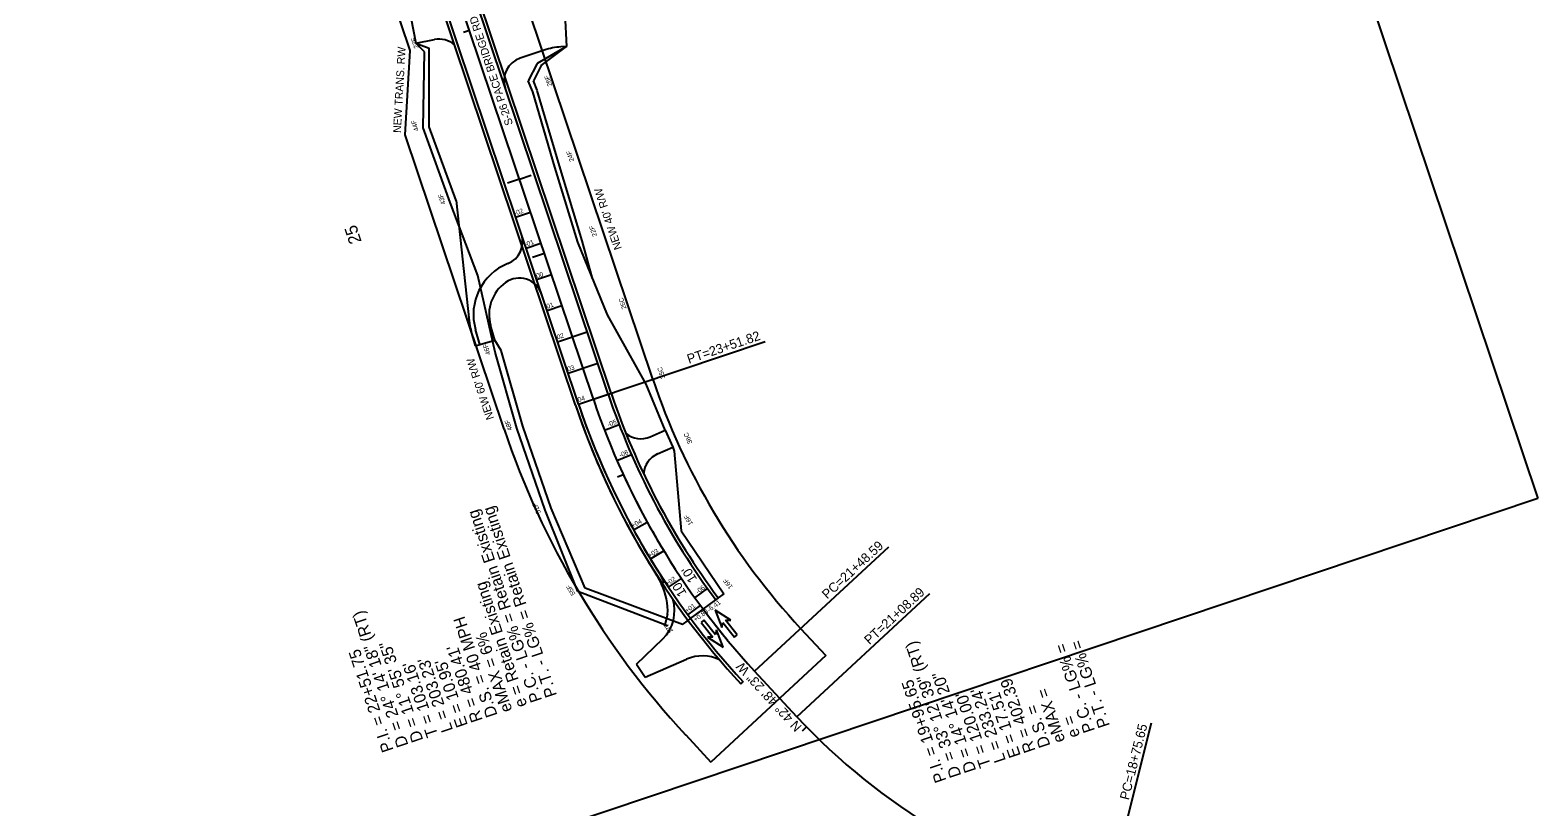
# Model space of a CAD drawing. Extents: x 1528853 to 1624411, y 1119753 to 1162242.
# Drawn here: x 1529554 to 1530516, y 1159228 to 1159723 of the extents above; entities that cross this region are included whole.
import ezdxf

# ---------------------------------------------------------------- set-up
doc = ezdxf.new("R2010")
doc.units = 0
for name, color, linetype in [('RD_EX_Road Text', 7, 'Continuous'), ('RD_HC_Cl', 7, 'Continuous'), ('RD_HC_Data', 7, 'Continuous'), ('RD_HC_Data_Tic', 7, 'Continuous'), ('RD_HC_TX_Sta50', 7, 'Continuous'), ('RD_PD_ALT1_TX', 7, 'Continuous'), ('RD_PD_CstnLmt', 7, 'Continuous'), ('RD_PD_CstnLmt_TX', 7, 'Continuous'), ('RD_PD_DR_ErosCtrl', 7, 'Continuous'), ('RD_PD_Driveway', 7, 'Continuous'), ('RD_PD_Final_TrvlWay', 7, 'Continuous'), ('RD_PD_Final_TX', 7, 'Continuous'), ('RD_PD_PaveShd', 7, 'Continuous'), ('RD_PD_RW', 7, 'Continuous'), ('RD_SHT_ShtClip', 7, 'Continuous'), ('RD_TX_Pipe_ElevEX', 7, 'Continuous')]:
    doc.layers.add(name, color=color, linetype=linetype)

msp = doc.modelspace()

# ---------------------------------------------------------------- linework, layer by layer
at = {"layer": 'RD_HC_Cl'}
for p, q in [((1529913.5, 1159487.74), (1529500.12, 1160718.34)), ((1530043.42, 1159285.14), (1530016.44, 1159314.26))]:
    msp.add_line(p, q, dxfattribs=at)
for centre, radius, start, end in [((1530368.9, 1159640.71), 480.41, 198.56801, 222.80647), ((1530338.63, 1159558.58), 402.39, 222.80647, 256.01743)]:
    msp.add_arc(centre, radius, start, end, dxfattribs=at)
at = {"layer": 'RD_HC_Data'}
for p, q in [((1529913.5, 1159487.74), (1530023.07, 1159524.55)), ((1530016.44, 1159314.26), (1530102.05, 1159393.56)), ((1530043.42, 1159285.14), (1530128.31, 1159363.77)), ((1530241.41, 1159168.11), (1530269.59, 1159281.29))]:
    msp.add_line(p, q, dxfattribs=at)
at = {"layer": 'RD_HC_Data_Tic'}
for p, q in [((1529834.47, 1159723), (1529830.68, 1159721.72)), ((1529866.31, 1159628.2), (1529858.73, 1159625.65)), ((1529866.31, 1159628.2), (1529873.89, 1159630.75)), ((1529932.61, 1159439.6), (1529928.98, 1159437.92)), ((1529983.59, 1159353.78), (1529980.38, 1159351.39)), ((1530049.53, 1159278.68), (1530046.66, 1159275.9))]:
    msp.add_line(p, q, dxfattribs=at)
at = {"layer": 'RD_PD_ALT1_TX'}
for p, q in [((1529863.89, 1159603.99), (1529873.37, 1159607.18)), ((1529870.58, 1159584.09), (1529880.06, 1159587.27)), ((1529877.27, 1159564.18), (1529886.75, 1159567.37)), ((1529883.95, 1159544.27), (1529893.43, 1159547.46)), ((1529890.64, 1159524.37), (1529909.6, 1159530.74)), ((1529897.33, 1159504.46), (1529916.29, 1159510.83)), ((1529904.02, 1159484.55), (1529922.97, 1159490.92)), ((1529920.62, 1159467.98), (1529929.95, 1159471.58)), ((1529928.59, 1159448.56), (1529937.76, 1159452.56)), ((1529939.16, 1159404.43), (1529947.93, 1159409.25)), ((1529949.9, 1159385.88), (1529958.44, 1159391.07)), ((1529961.44, 1159367.81), (1529969.74, 1159373.38)), ((1529978.28, 1159361.05), (1529986.42, 1159366.87)), ((1529973.75, 1159350.27), (1529981.81, 1159356.19))]:
    msp.add_line(p, q, dxfattribs=at)
at = {"layer": 'RD_PD_CstnLmt'}
for p, q in [((1529800.23, 1159714.99), (1529808.8, 1159711.75)), ((1529808.82, 1159661.63), (1529808.8, 1159711.75)), ((1529896.42, 1159712.77), (1529877.64, 1159702.02)), ((1529877.64, 1159702.02), (1529871.97, 1159690.97)), ((1529874.9, 1159683.83), (1529871.97, 1159690.97)), ((1529888.97, 1159635.81), (1529874.9, 1159683.83)), ((1529825.99, 1159614.66), (1529808.82, 1159661.63)), ((1529903.55, 1159587.97), (1529888.97, 1159635.81)), ((1529825.99, 1159614.66), (1529834.19, 1159537.82)), ((1529922.43, 1159541.56), (1529903.55, 1159587.97)), ((1529947.2, 1159497.28), (1529922.43, 1159541.56)), ((1529838.2, 1159521.77), (1529835.45, 1159531.38)), ((1529838.2, 1159521.77), (1529841.08, 1159522.59)), ((1529854.66, 1159518.8), (1529850.7, 1159525.35)), ((1529868.5, 1159470.51), (1529854.66, 1159518.8)), ((1529959.39, 1159468.06), (1529947.2, 1159497.28)), ((1529886.49, 1159418.33), (1529868.5, 1159470.51)), ((1529959.39, 1159468.06), (1529964.2, 1159457.07)), ((1529964.2, 1159457.07), (1529965.03, 1159454.54)), ((1529965.03, 1159454.54), (1529969.53, 1159403.71)), ((1529908.3, 1159367.1), (1529886.49, 1159418.33)), ((1529969.53, 1159403.71), (1529996.75, 1159363.58)), ((1529970.35, 1159343.91), (1529908.3, 1159367.1)), ((1529996.75, 1159363.58), (1529993.22, 1159360.94)), ((1529970.35, 1159343.91), (1529973.97, 1159346.61))]:
    msp.add_line(p, q, dxfattribs=at)
for centre, radius, start, end in [((1529871.97, 1159541.85), 38, 186.08768, 195.99377), ((1530368.9, 1159640.71), 480.41, 204.74857, 210.7118)]:
    msp.add_arc(centre, radius, start, end, dxfattribs=at)
at = {"layer": 'RD_PD_DR_ErosCtrl'}
for p, q in [((1529805.84, 1159709.46), (1529800.23, 1159714.99)), ((1529880.31, 1159700.65), (1529896.42, 1159712.77)), ((1529804.82, 1159660.93), (1529805.84, 1159709.46)), ((1529880.31, 1159700.65), (1529875.27, 1159690.83)), ((1529877.68, 1159684.97), (1529875.27, 1159690.83)), ((1529891.84, 1159636.67), (1529877.74, 1159684.83)), ((1529822.24, 1159613.27), (1529804.82, 1159660.93)), ((1529906.42, 1159588.84), (1529891.84, 1159636.67)), ((1529839.75, 1159566.67), (1529822.24, 1159613.27)), ((1529912.99, 1159564.76), (1529906.42, 1159588.84)), ((1529850.78, 1159517.8), (1529839.75, 1159566.67)), ((1529864.68, 1159469.3), (1529850.78, 1159517.8)), ((1529882.71, 1159417.03), (1529864.68, 1159469.3)), ((1529903.7, 1159365.14), (1529882.71, 1159417.03)), ((1529960.91, 1159343.1), (1529903.7, 1159365.14))]:
    msp.add_line(p, q, dxfattribs=at)
at = {"layer": 'RD_PD_Driveway'}
for p, q in [((1529797.04, 1159731.42), (1529800.23, 1159714.99)), ((1529895.32, 1159733.63), (1529896.42, 1159712.77)), ((1529800.23, 1159714.99), (1529812.1, 1159717.29)), ((1529882.21, 1159710.55), (1529866.76, 1159705.36)), ((1529896.42, 1159712.77), (1529892.83, 1159712.58)), ((1529882.23, 1159580.8), (1529874.65, 1159578.26)), ((1529841.08, 1159522.59), (1529838.33, 1159532.21)), ((1529850.7, 1159525.35), (1529847.94, 1159534.96)), ((1529841.08, 1159522.59), (1529850.7, 1159525.35)), ((1529949.72, 1159463.83), (1529959.39, 1159468.06)), ((1529959.39, 1159468.06), (1529964.2, 1159457.07)), ((1529954.54, 1159452.84), (1529964.2, 1159457.07)), ((1529941.05, 1159318.59), (1529957.76, 1159334.87)), ((1529941.05, 1159318.59), (1529946.63, 1159310.29)), ((1529946.63, 1159310.29), (1529973.04, 1159321.87))]:
    msp.add_line(p, q, dxfattribs=at)
for centre, radius, start, end in [((1529814.96, 1159702.57), 15, 48.49444, 100.99079), ((1529894.94, 1159672.63), 40, 93.03139, 108.56801), ((1529871.54, 1159691.14), 15, 108.56801, 198.56801), ((1529853.36, 1159588.26), 15, 291.8606, 18.56801), ((1529871.97, 1159541.85), 35, 111.8606, 195.99377), ((1529871.97, 1159541.85), 25, 125.25691, 195.99377), ((1529866.2, 1159550.02), 15, 18.56801, 125.25691), ((1529943.71, 1159477.58), 15, 231.38509, 293.6342), ((1529960.55, 1159439.1), 15, 113.6342, 175.88331), ((1529940.32, 1159352.78), 25, 314.24892, 17.32424), ((1529983.08, 1159298.97), 25, 64.05628, 113.66726)]:
    msp.add_arc(centre, radius, start, end, dxfattribs=at)
at = {"layer": 'RD_PD_Final_TrvlWay'}
for p, q in [((1529922.97, 1159490.92), (1529689.19, 1160186.88)), ((1529904.02, 1159484.55), (1529670.23, 1160180.51)), ((1529955.84, 1159376.35), (1529958.76, 1159370.61)), ((1529975.57, 1159347.8), (1529991.61, 1159359.75))]:
    msp.add_line(p, q, dxfattribs=at)
for radius, end in [(470.41, 216.67502), (490.41, 212.61974), (490.41, 222.80647)]:
    msp.add_arc((1530368.9, 1159640.71), radius, 198.56801, end, dxfattribs=at)
at = {"layer": 'RD_PD_Final_TX'}
for p, q in [((1529983.98, 1159346.73), (1529982.22, 1159345.33)), ((1529982.22, 1159345.33), (1529989.7, 1159335.95)), ((1529991.46, 1159337.35), (1529983.98, 1159346.73)), ((1530001.18, 1159346.69), (1529991.29, 1159353.19)), ((1529991.29, 1159353.19), (1529995.43, 1159342.1)), ((1529995.43, 1159342.1), (1529996.12, 1159345.34)), ((1529996.12, 1159345.34), (1530003.6, 1159335.95)), ((1530005.36, 1159337.36), (1529997.87, 1159346.74)), ((1529997.87, 1159346.74), (1530001.18, 1159346.69)), ((1529986.4, 1159336), (1529996.29, 1159329.5)), ((1529989.7, 1159335.95), (1529986.4, 1159336)), ((1529992.14, 1159340.58), (1529991.46, 1159337.35)), ((1529996.29, 1159329.5), (1529992.14, 1159340.58)), ((1530003.6, 1159335.95), (1530005.36, 1159337.36))]:
    msp.add_line(p, q, dxfattribs=at)
at = {"layer": 'RD_PD_PaveShd'}
for p, q in [((1529902.12, 1159483.92), (1529787.4, 1159825.43)), ((1529924.87, 1159491.56), (1529810.14, 1159833.1)), ((1529954.1, 1159375.36), (1529956.97, 1159369.71)), ((1529993.22, 1159360.94), (1529991.61, 1159359.75)), ((1529960.92, 1159350.45), (1529959.04, 1159343.83)), ((1529973.97, 1159346.61), (1529975.57, 1159347.8)), ((1529959.04, 1159343.83), (1529960.91, 1159343.1)), ((1530007.64, 1159306.11), (1530009.11, 1159307.47))]:
    msp.add_line(p, q, dxfattribs=at)
for centre, radius, start, end in [((1530368.9, 1159640.71), 468.41, 198.56801, 216.67502), ((1530368.9, 1159640.71), 492.41, 198.56801, 212.60819), ((1530368.9, 1159640.71), 492.41, 198.56801, 222.80647), ((1529922.39, 1159352.58), 38.59, 356.82864, 26.35466)]:
    msp.add_arc(centre, radius, start, end, dxfattribs=at)
at = {"layer": 'RD_PD_RW'}
for p, q in [((1529796.55, 1159710.26), (1529748.79, 1159852.45)), ((1529951.41, 1159500.47), (1529872.39, 1159735.73)), ((1529793.51, 1159656.49), (1529796.55, 1159710.26)), ((1529856.62, 1159468.63), (1529793.51, 1159656.49)), ((1530045.79, 1159341.45), (1530061.82, 1159324.14)), ((1530061.82, 1159324.14), (1529988.45, 1159256.19)), ((1529972.42, 1159273.49), (1529988.45, 1159256.19))]:
    msp.add_line(p, q, dxfattribs=at)
for radius, start, end in [(440.41, 198.56801, 222.80647), (540.41, 198.56801, 222.80647), (480.41, 216.67502, 219.65664), (480.41, 216.67502, 219.65664)]:
    msp.add_arc((1530368.9, 1159640.71), radius, start, end, dxfattribs=at)
at = {"layer": 'RD_SHT_ShtClip'}
for p, q in [((1529895.79, 1161273.06), (1530516.23, 1159424.4)), ((1530516.23, 1159424.4), (1529473.4, 1159074.4))]:
    msp.add_line(p, q, dxfattribs=at)

# ---------------------------------------------------------------- texts
at = {"layer": 'RD_EX_Road Text'}
msp.add_text('S-26 PACE BRIDGE RD', height=5, rotation=108.55272, dxfattribs=at).set_placement((1529862.31, 1159663.38))
at = {"layer": 'RD_HC_Data'}
for s, height, rotation, p in [('PT=23+51.82', 6, 18.56801, (1529974.47, 1159510.33)), ('P.C. - LG% = Retain Existing', 7.5, 108.55453, (1529880.89, 1159295.76)), ('P.T. - LG% = Retain Existing', 7.5, 108.55453, (1529890.37, 1159298.94)), ('PC=21+48.59', 6, 42.80647, (1530062.77, 1159359.9)), ('e = Retain Existing', 7.5, 108.55453, (1529871.41, 1159292.58)), ('PT=21+08.89', 6, 42.80647, (1530089.75, 1159330.78)), ('    = 24%%d 14\' 18" (RT)', 7.5, 108.55453, (1529795.56, 1159267.12)), ('D.S. = 40 MPH', 7.5, 108.55453, (1529852.45, 1159286.21)), ('eMAX = 6%', 7.5, 108.55453, (1529861.93, 1159289.39)), ('P.I. = 22+51.75', 7.5, 108.55453, (1529786.08, 1159263.94)), ('D = 11%%d 55\' 35"', 7.5, 108.55453, (1529805.04, 1159270.3)), ("R = 480.41'", 7.5, 108.55453, (1529842.97, 1159283.03)), ('    = 33%%d 12\' 39" (RT)', 7.5, 108.55722, (1530148.39, 1159247.71)), ('P.C. - LG% = ', 7.5, 108.55722, (1530233.71, 1159276.36)), ('P.T. - LG% = ', 7.5, 108.55722, (1530243.19, 1159279.54)), ("T = 103.16'", 7.5, 108.55453, (1529814.52, 1159273.48)), ("L = 203.23'", 7.5, 108.55453, (1529824, 1159276.67)), ("E = 10.95'", 7.5, 108.55453, (1529833.49, 1159279.85)), ('N 42%%d 48\' 23" W', 6, 132.80647, (1530046.96, 1159279.05)), ('P.I. = 19+95.65', 7.5, 108.55722, (1530138.91, 1159244.53)), ('D = 14%%d 14\' 20"', 7.5, 108.55722, (1530157.87, 1159250.9)), ("R = 402.39'", 7.5, 108.55722, (1530195.79, 1159263.63)), ("T = 120.00'", 7.5, 108.55722, (1530167.35, 1159254.08)), ("L = 233.24'", 7.5, 108.55722, (1530176.83, 1159257.26)), ("E = 17.51'", 7.5, 108.55722, (1530186.31, 1159260.44)), ('eMAX = ', 7.5, 108.55722, (1530214.75, 1159269.99)), ('D.S. = ', 7.5, 108.55722, (1530205.27, 1159266.81)), ('e = ', 7.5, 108.55722, (1530224.23, 1159273.17)), ('PC=18+75.65', 6, 76.01743, (1530255.17, 1159231.66)), ('D', 7.5, 108.55453, (1529795.56, 1159267.12)), ('D', 7.5, 108.55722, (1530148.39, 1159247.71))]:
    msp.add_text(s, height=height, rotation=rotation, dxfattribs=at).set_placement(p)
at = {"layer": 'RD_HC_TX_Sta50'}
msp.add_text('25', height=8, rotation=108.56801, dxfattribs=at).set_placement((1529765.77, 1159588.35))
at = {"layer": 'RD_PD_ALT1_TX'}
for s, rotation, p in [('-02', 18.56801, (1529863.44, 1159604.9)), ('-01', 18.56801, (1529870.18, 1159584.99)), ('00', 18.56801, (1529877.52, 1159564.95)), ('01', 18.56801, (1529884.13, 1159545.48)), ('02', 18.56801, (1529890.74, 1159525.81)), ('03', 18.56801, (1529897.41, 1159505.43)), ('04', 18.56801, (1529904.07, 1159485.85)), ('-05', 21.07256, (1529923.09, 1159470.02)), ('-06', 23.57712, (1529930.69, 1159450.46)), ('+04', 28.80357, (1529938.68, 1159405.55)), ('+03', 31.30812, (1529949.48, 1159386.45)), ('+02', 33.81268, (1529960.62, 1159368.46)), ('-06', 36.67502, (1529980.2, 1159363.34)), ('+01', 36.67502, (1529973.35, 1159351.16))]:
    msp.add_text(s, height=3, rotation=rotation, dxfattribs=at).set_placement(p)
at = {"layer": 'RD_PD_CstnLmt_TX'}
for s, rotation, p in [('27F', 108.56801, (1529802.16, 1159712.14)), ('26F', 108.56801, (1529887.23, 1159687.97)), ('44F', 108.56801, (1529802.18, 1159659.41)), ('24F', 108.56801, (1529901.29, 1159639.95)), ('43F', 108.56801, (1529819.36, 1159612.43)), ('22F', 108.56801, (1529915.88, 1159592.11)), ('26C', 108.56801, (1529934.75, 1159545.7)), ('46F', 108.56801, (1529848.02, 1159516.57)), ('35C', 108.78534, (1529959.51, 1159501.46)), ('48F', 108.78534, (1529861.87, 1159468.25)), ('36C', 114.74856, (1529976.84, 1159459.98)), ('51F', 114.74856, (1529880.13, 1159415.4)), ('16F', 120.7118, (1529977.28, 1159408.31)), ('55F', 120.7118, (1529902.28, 1159363.53)), ('16F', 126.67502, (1530002.69, 1159368)), ('17F', 126.67502, (1529964.73, 1159339.73))]:
    msp.add_text(s, height=3, rotation=rotation, dxfattribs=at).set_placement(p)
at = {"layer": 'RD_PD_Final_TX'}
for p in [(1529979.94, 1159372.9), (1529973.27, 1159363.97)]:
    msp.add_text("10'", height=6, rotation=121.57269, dxfattribs=at).set_placement(p)
at = {"layer": 'RD_PD_RW'}
for s, rotation, p in [('NEW TRANS. RW', 86.76658, (1529790.63, 1159657.59)), ("NEW 40' R/W", 108.55272, (1529931.74, 1159584.09)), ("NEW 60' R/W", 108.55272, (1529850.19, 1159475.59))]:
    msp.add_text(s, height=5, rotation=rotation, dxfattribs=at).set_placement(p)
at = {"layer": 'RD_TX_Pipe_ElevEX'}
for s, p in [('+0.88', (1529978.73, 1159345.52)), ('-6.41', (1529987.58, 1159351.8))]:
    msp.add_text(s, height=3, rotation=36.67502, dxfattribs=at).set_placement(p)

doc.saveas('drawing.dxf')
